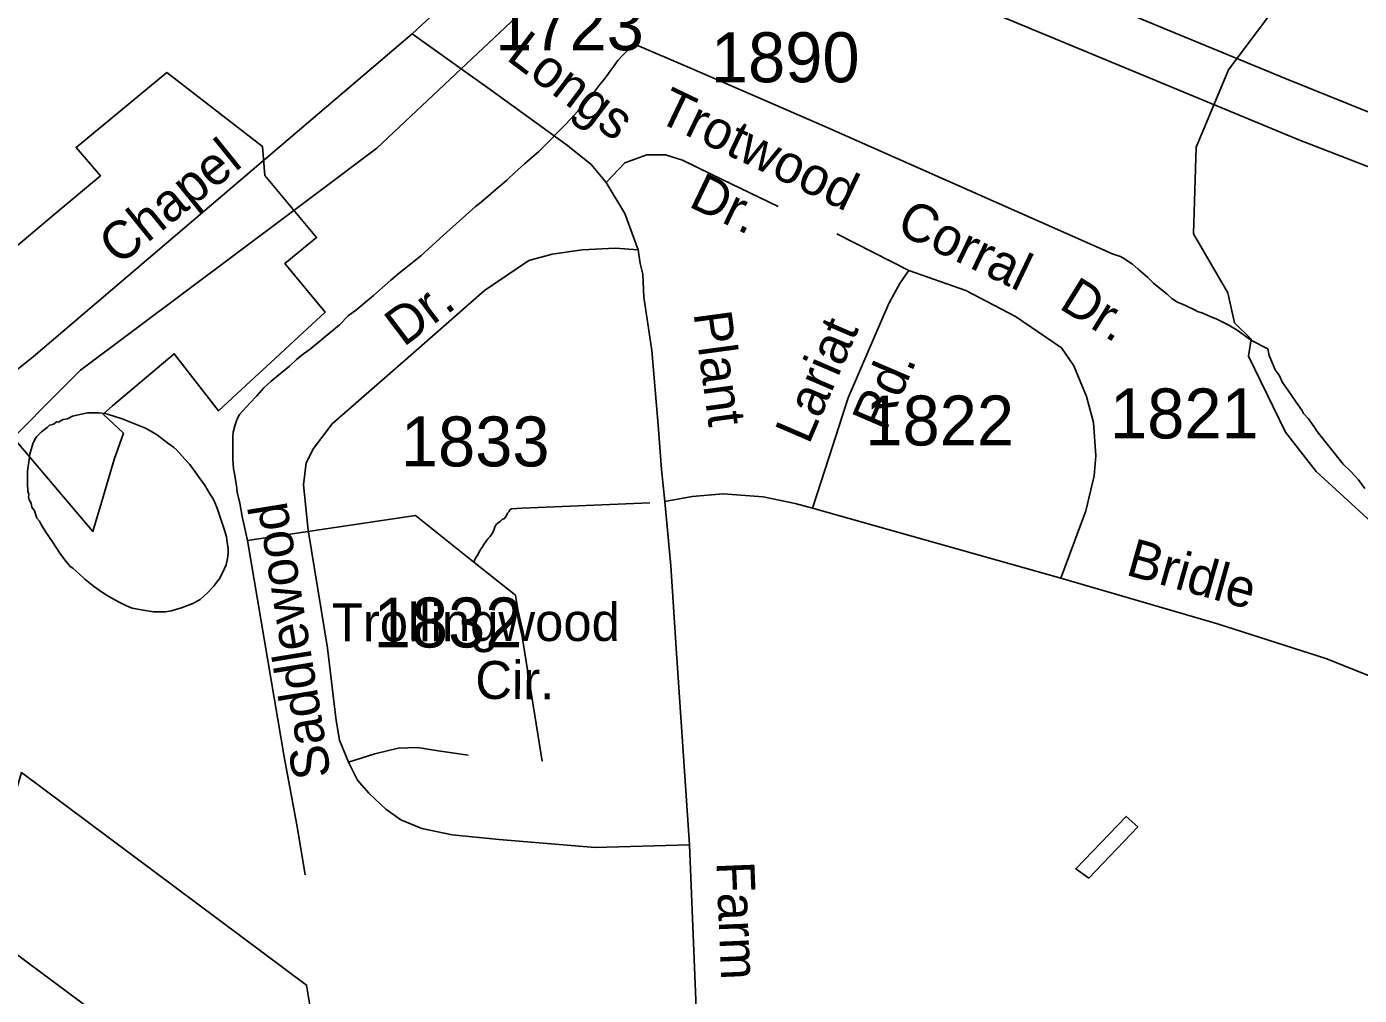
# Model space of a CAD drawing. Extents: x 2260773 to 2342389, y 552869 to 618546.
# Drawn here: x 2323921 to 2327254, y 582598 to 585022 of the extents above; entities that cross this region are included whole.
import ezdxf

# ---------------------------------------------------------------- set-up
doc = ezdxf.new("R2010")
doc.units = 0
for name, color, linetype in [('Exist Boundary Political City Limit New', 7, 'Continuous'), ('Exist Boundary Political Urban Extension UEB', 7, 'Continuous'), ('Exist Hydrographic Creek Single Shore', 7, 'Continuous'), ('Exist Hydrographic Misc Water Feature', 7, 'Continuous'), ('Exist Road Secondary Type 51 Attributed', 7, 'Continuous'), ('Exist Road Secondary Type 51 Label', 7, 'Continuous'), ('Exist Road Secondary Type 51 Number Label', 7, 'Continuous'), ('Map Preparation Boundary City Limit Buffer Line', 7, 'Continuous')]:
    doc.layers.add(name, color=color, linetype=linetype)

msp = doc.modelspace()

# ---------------------------------------------------------------- linework, layer by layer
at = {"layer": 'Exist Boundary Political City Limit New'}
for points in [[(2323668.2, 584281.2), (2323989.8, 584551.6), (2324105.5, 584648.9), (2324044.5, 584719.9), (2324271.2, 584907.1), (2324510.5, 584722.4), (2324516.8, 584649.4), (2324646.2, 584494.4), (2324567, 584429.8), (2324667.8, 584307.8), (2324578, 584224.9), (2324531.8, 584182), (2324491.8, 584144.8), (2324400.8, 584060.6), (2324290.2, 584203.5), (2324136, 584073), (2324112, 584052.8), (2324162.8, 584005.2), (2324140, 583939.2), (2324133, 583916.4), (2324103.8, 583817.4), (2324099.8, 583803.6), (2324086.5, 583758.7), (2323892, 583988.1)], [(2324673.5, 582308.4), (2324709.2, 582053.6), (2324723, 581957), (2324744, 581807.5), (2324535.8, 581891.1), (2324543.5, 581918.2), (2324427.2, 581964.1), (2324488.8, 582124.9), (2324365, 582177.6), (2324302, 582017.8), (2324046.8, 582140.8), (2324103.2, 582284.9), (2324184, 582486.4), (2324094.5, 582552.9), (2323814, 582761.1), (2323794, 582771.3), (2323907.8, 583155.7), (2324621.2, 582624.2), (2324673.5, 582308.4)]]:
    msp.add_lwpolyline(points, dxfattribs=at)
at = {"layer": 'Exist Boundary Political Urban Extension UEB'}
msp.add_line((2324646.2, 584604.9), (2324582.6, 584557.2), dxfattribs=at)
for points in [[(2329076.9, 583924.2), (2328749.3, 584100.5), (2327102.5, 584738.6), (2325517.5, 585397.2), (2325007.6, 584916.5)], [(2325007.6, 584916.5), (2324797, 584718), (2324646.2, 584604.9)], [(2324582.6, 584557.2), (2324055.9, 584162.3), (2323829.7, 583936.1)]]:
    msp.add_lwpolyline(points, dxfattribs=at)
at = {"layer": 'Exist Hydrographic Creek Single Shore'}
msp.add_lwpolyline([(2328673.6, 582831.9), (2328655.5, 582949.3), (2328477.5, 583188.3), (2328318.4, 583329.5), (2327950.6, 583432.7), (2327732.4, 583532.2), (2327548.5, 583603.6), (2327372.5, 583701.5), (2327145.5, 583908.9), (2327069.5, 584007.6), (2326976.6, 584197.4), (2326983.5, 584240.4), (2326941.5, 584281.3), (2326924.5, 584356.1), (2326839.4, 584503.6), (2326845.5, 584720.5), (2326926.5, 584914.1), (2327033.4, 585056.2)], dxfattribs=at)
at = {"layer": 'Exist Hydrographic Misc Water Feature'}
for points in [[(2324473.1, 583736.2), (2324460, 583796.1), (2324454.2, 583829.8), (2324447.2, 583857.6), (2324445.4, 583873.8), (2324442.9, 583887.9), (2324440.9, 583903.6), (2324438.6, 583915.7), (2324436.8, 583939.5), (2324436.4, 583945.6), (2324436.4, 583955.4), (2324436.4, 583965.5), (2324436.6, 583971.6), (2324436.2, 583977.7), (2324436.2, 583995.6), (2324437.8, 584007.5), (2324441.7, 584023.5), (2324445.4, 584035.5), (2324449.7, 584045.9), (2324453.2, 584051.8), (2324479.2, 584079.9), (2324496.7, 584098), (2324514.5, 584118.4), (2324532.5, 584134.7), (2324546.5, 584146.8), (2324578.5, 584172.9), (2324595.9, 584189.3), (2324613.5, 584203.2), (2324629.7, 584215.4), (2324703.2, 584276.2), (2324724.7, 584298.5), (2324746.4, 584314.6), (2324768.2, 584332.9), (2324788.5, 584349.3), (2324831.7, 584387.8), (2324853.5, 584406), (2324873.1, 584422.1), (2324906.8, 584448.3), (2324962.5, 584499.1), (2325043.3, 584571.7), (2325053.4, 584579.9), (2325075.1, 584598.2), (2325101, 584620.6), (2325109.2, 584626.7), (2325122.7, 584638.8), (2325142.2, 584657), (2325166.2, 584678.9), (2325202, 584709.6), (2325208, 584715.6), (2325269.1, 584778.2), (2325299, 584810.6), (2325330.6, 584846.8), (2325342.3, 584860.8), (2325354.4, 584876.9), (2325364, 584889.2), (2325372, 584899.3), (2325381.7, 584913.3), (2325389.7, 584923.5), (2325399.7, 584937.4), (2325411, 584949.5), (2325417.1, 584955.8), (2325425.3, 584963.9), (2325440.7, 584977.8), (2325579.3, 584919.3), (2325915, 584773), (2326637.8, 584453), (2326656.1, 584447), (2326666.1, 584441.4), (2326672.3, 584437.3), (2326686.4, 584427.5), (2326700.6, 584415.6), (2326718.2, 584399.9), (2326725, 584394.1), (2326738.9, 584380.2), (2326753.1, 584368.3), (2326772.9, 584352.4), (2326785.5, 584340.8), (2326799.4, 584333), (2326813.1, 584326.9), (2326821.1, 584323.2), (2326841.6, 584313.2), (2326849.4, 584309.2), (2326859.5, 584305.7), (2326879.4, 584297.9), (2326897.6, 584289.8), (2326905.4, 584286.2), (2326917.7, 584280.3), (2326925.5, 584276.3), (2326935.6, 584270.3), (2326947.9, 584262.4), (2326959.7, 584254.5), (2326975.9, 584242.8), (2326983.9, 584237.1), (2327024.8, 584215.6)], [(2327024.8, 584215.6), (2327028.4, 584199.6), (2327034.6, 584183.6), (2327043.2, 584163.7), (2327053.3, 584149.6), (2327061.2, 584131.8), (2327075.4, 584111.8), (2327095.5, 584082.4), (2327110.1, 584062.4), (2327113.9, 584054.5), (2327126.5, 584040.5), (2327140.6, 584020.5), (2327148.4, 584008.8), (2327213.4, 583927.6), (2327231.4, 583909.9), (2327251.9, 583887.8), (2327267.9, 583866.3)], [(2324248.1, 583999.5), (2324235.8, 584007.5), (2324225.8, 584013.4), (2324218, 584017), (2324159.8, 584040.4), (2324141.7, 584046.4), (2324123.5, 584052.3), (2324115.7, 584053.9), (2324101.7, 584056.1), (2324097.8, 584055.8), (2324091.9, 584055.9), (2324073.6, 584055.8), (2324061.7, 584053.5), (2324053.8, 584051.5), (2324043.5, 584049.4), (2324035.5, 584047.3), (2324023.4, 584041), (2324012.1, 584039.1), (2324000, 584032.8), (2323995.7, 584033), (2323990, 584028.6), (2323985.9, 584026.8), (2323977.9, 584024.8), (2323972.1, 584018.7), (2323958.2, 584008.3), (2323954.1, 584004.4), (2323950, 584000.2), (2323946.3, 583996.3), (2323942.4, 583990.4), (2323940.4, 583986.2), (2323938.5, 583982), (2323936.5, 583978.3), (2323928.9, 583952.3), (2323926.8, 583932.3), (2323925, 583922), (2323923.1, 583910.2), (2323923.3, 583904.1), (2323923.3, 583896), (2323923.3, 583886.2), (2323923.5, 583872), (2323923.7, 583866.2), (2323924.2, 583860.1), (2323926.2, 583852.1), (2323926, 583846), (2323927.6, 583838.1), (2323932.4, 583830.1), (2323934, 583820.1), (2323940.4, 583810.2), (2323946.3, 583792.3), (2323952.7, 583784.5), (2323957, 583776.5), (2323969.1, 583756.8), (2323985.5, 583732.9), (2324003.7, 583705), (2324015.4, 583689), (2324029.6, 583671.5), (2324036.1, 583667.3), (2324062.4, 583643.8), (2324066.3, 583639.6), (2324088, 583622.2), (2324110.6, 583606.2), (2324126.3, 583596.5), (2324150.7, 583582.7), (2324170.4, 583572.8), (2324185.2, 583567), (2324217, 583561.4), (2324238.9, 583557.7), (2324252.9, 583558), (2324268.6, 583558.1), (2324283, 583560), (2324296.9, 583564.3), (2324308.6, 583568.3), (2324336.7, 583578.6), (2324354.6, 583588.9), (2324372.2, 583604.9), (2324388, 583621.2), (2324396, 583631.3), (2324402.1, 583639.4), (2324411.8, 583657.4), (2324419.6, 583675.7), (2324423.5, 583691.7), (2324425.1, 583703.6), (2324425.3, 583717.4), (2324422.8, 583731.5), (2324420.6, 583745.7), (2324414.4, 583767.3), (2324397.6, 583817.3), (2324389.4, 583837.1), (2324385.7, 583843), (2324379.4, 583853.3), (2324373.4, 583863), (2324367.5, 583872.9), (2324329.1, 583926.5), (2324316.6, 583940.1), (2324296.3, 583962.2), (2324288.3, 583969.9), (2324274.2, 583979.8), (2324248.1, 583999.5)], [(2325479.5, 583830.9), (2325159.8, 583817.3), (2325133.8, 583815.2), (2325129.7, 583812.9), (2325127.8, 583809.2), (2325123.7, 583804.9), (2325120.2, 583796.9), (2325115.9, 583791.1), (2325110, 583788.7), (2325105.9, 583784.9), (2325100.1, 583780.9), (2325096, 583777), (2325092.1, 583770.7), (2325090.3, 583764.9), (2325086.4, 583756.6), (2325080.4, 583746.5), (2325074.7, 583740.5), (2325070.4, 583734.7), (2325064.7, 583726.6), (2325060.8, 583720.3), (2325056.7, 583714.4), (2325050.9, 583704.3), (2325048.9, 583700.2), (2325045, 583694.3), (2325042.9, 583690.1), (2325039, 583682.2)], [(2325039, 583682.2), (2324893.8, 583798.5), (2324473.1, 583736.2)], [(2324617.8, 582900.1), (2324598.4, 583015.7), (2324564.9, 583195.1), (2324473.1, 583736.2)], [(2325210.4, 583184.4), (2325143.8, 583599.5), (2325039, 583682.2)], [(2326576.9, 582891.2), (2326544.7, 582915.1), (2326671, 583046.1), (2326699.5, 583020.3), (2326576.9, 582891.2)]]:
    msp.add_lwpolyline(points, dxfattribs=at)
at = {"layer": 'Exist Road Secondary Type 51 Attributed'}
for p, q in [((2326127.5, 584411.8), (2325947, 584503.6)), ((2325886.4, 583816.9), (2326507.6, 583642.2))]:
    msp.add_line(p, q, dxfattribs=at)
for points in [[(2325403.9, 585580.5), (2325312.1, 585467.2), (2325198.2, 585337.2), (2325100.6, 585221.8), (2324985.3, 585097.5), (2324885.4, 585004.2)], [(2325403.9, 585580.5), (2327070.9, 584891.5), (2327889.1, 584561.4), (2329051.2, 584078.7), (2329166.4, 584028.3), (2329221.1, 584004.4), (2329309, 583947.7), (2329383.2, 583887.2), (2329447.6, 583830.5), (2329559.9, 583704.4), (2329766.9, 583446.5), (2329852.9, 583325.3), (2329899.8, 583229.5), (2329917.3, 583184.6)], [(2324885.4, 585004.2), (2323937.9, 584196.7), (2323711.5, 584014.7), (2323367.7, 583704.6), (2322777.6, 583052.4), (2322674, 582938), (2322644.5, 582899.3)], [(2324885.4, 585004.2), (2325007.6, 584916.5), (2325074, 584868.8), (2325273.7, 584724.5), (2325332.5, 584676.8), (2325370.2, 584632.4)], [(2325370.2, 584632.4), (2325416.8, 584681.2), (2325472.2, 584701.2), (2325518.8, 584701.2), (2325561, 584687.9), (2325634.2, 584652.3), (2325800.6, 584572.4)], [(2325370.2, 584632.4), (2325416.8, 584554.7), (2325450, 584463.6)], [(2324725.7, 583181.6), (2324703.5, 583237.1), (2324694.6, 583285.9), (2324673.5, 583466.9), (2324624.7, 583762.1), (2324613.6, 583875.3), (2324620.3, 583930.8), (2324638, 583966.4), (2324684.6, 584028.5), (2324888.7, 584206.1), (2325066.2, 584361.5), (2325177.2, 584437), (2325234.8, 584452.5), (2325310.3, 584463.6), (2325392.4, 584468.1), (2325450, 584463.6)], [(2325450, 584463.6), (2325455.6, 584429.2), (2325462.3, 584402.6), (2325464.5, 584344.9), (2325484.4, 584211.7), (2325500, 584025.2), (2325508.8, 583914.2), (2325517.3, 583833.9)], [(2325886.4, 583816.9), (2325927.8, 583945.6), (2325975.1, 584093.6), (2326029.8, 584219.4), (2326077.2, 584329), (2326105.3, 584380.8), (2326127.5, 584411.8)], [(2326507.6, 583642.2), (2326569.7, 583811), (2326590.4, 583898.3), (2326594.8, 583948.6), (2326588.9, 584031.5), (2326571.2, 584096.6), (2326540.1, 584173.6), (2326509.1, 584218), (2326393.7, 584296.4), (2326269.4, 584361.5), (2326127.5, 584411.8)], [(2325517.3, 583833.9), (2325585.4, 583846.5), (2325663, 583853.1), (2325762.8, 583845.8), (2325842.9, 583828.6), (2325886.4, 583816.9)], [(2325517.3, 583833.9), (2325532.1, 583673.3), (2325545.4, 583466.9), (2325578.7, 582974.8)], [(2326507.6, 583642.2), (2326898.8, 583527.6), (2327172.4, 583440.2), (2327463.8, 583323.3), (2327602.8, 583270), (2328057.6, 583139.1), (2328114.6, 583122), (2328158.2, 583100.6), (2328189.3, 583072.5), (2328205.5, 583041.4), (2328218.9, 583005.9), (2328221.8, 582971.8), (2328214.4, 582934.8)], [(2324725.7, 583181.6), (2324791.5, 583202.5), (2324850.3, 583216.4), (2324898.2, 583218.8), (2324949.8, 583210.5), (2325025.2, 583199.4)], [(2325578.7, 582974.8), (2325342.8, 582968.1), (2325102.8, 582988.5), (2324985.3, 582999.6), (2324909.5, 583015.5), (2324856.6, 583037.3), (2324818.9, 583063.9), (2324776.7, 583103.9), (2324748.2, 583136.8), (2324725.7, 583181.6)], [(2325578.7, 582974.8), (2325616.4, 582055), (2325639.4, 581485.9), (2325639.1, 581473.5), (2325637.8, 581413)]]:
    msp.add_lwpolyline(points, dxfattribs=at)
at = {"layer": 'Map Preparation Boundary City Limit Buffer Line'}
for points in [[(2323668.2, 584281.2), (2323989.8, 584551.6), (2324105.5, 584648.9), (2324044.5, 584719.9), (2324271.2, 584907.1), (2324510.5, 584722.4), (2324516.8, 584649.4), (2324646.2, 584494.4), (2324567, 584429.8), (2324667.8, 584307.8), (2324578, 584224.9), (2324531.8, 584182), (2324491.8, 584144.8), (2324400.8, 584060.6), (2324290.2, 584203.5), (2324136, 584073), (2324112, 584052.8), (2324162.8, 584005.2), (2324140, 583939.2), (2324133, 583916.4), (2324103.8, 583817.4), (2324099.8, 583803.6), (2324086.5, 583758.7), (2323892, 583988.1)], [(2324673.5, 582308.4), (2324709.2, 582053.6), (2324723, 581957), (2324744, 581807.5), (2324535.8, 581891.1), (2324543.5, 581918.2), (2324427.2, 581964.1), (2324488.8, 582124.9), (2324365, 582177.6), (2324302, 582017.8), (2324046.8, 582140.8), (2324103.2, 582284.9), (2324184, 582486.4), (2324094.5, 582552.9), (2323814, 582761.1), (2323794, 582771.3), (2323907.8, 583155.7), (2324621.2, 582624.2), (2324673.5, 582308.4)]]:
    msp.add_lwpolyline(points, dxfattribs=at)

# ---------------------------------------------------------------- texts
at = {"layer": 'Exist Road Secondary Type 51 Label'}
for s, rotation, p in [('Longs', 322.9611, (2325117.5, 584941.1)), ('Trotwood', 334.4068, (2325492.8, 584787.3)), ('Chapel', 38.9075, (2324151.2, 584422.2)), ('Dr.', 334.4068, (2325573.4, 584573.3)), ('Corral', 334.44, (2326091.9, 584507.9)), ('Dr.', 328.2331, (2326499.7, 584318.7)), ('Dr.', 37.0525, (2324863.8, 584219.1)), ('Plant', 277.6938, (2325588.4, 584305.1)), ('Lariat', 66.7314, (2325877.2, 583974.3)), ('Rd.', 66.7314, (2326069.4, 584005.5)), ('Saddlewood', 99.2202, (2324682.4, 583147.3)), ('Bridle', 344.3219, (2326666.8, 583651.3)), ('Trollingwood', 0.0884, (2324684.3, 583484)), ('Cir.', 359.6837, (2325042.8, 583340.1)), ('Farm', 272.3372, (2325645.7, 582931.9))]:
    msp.add_text(s, height=95, rotation=rotation, dxfattribs=at).set_placement(p)
at = {"layer": 'Exist Road Secondary Type 51 Number Label'}
for s, p in [('1723', (2325092.7, 584962.8)), ('1890', (2325632.1, 584882.8)), ('1821', (2326630.3, 583991.8)), ('1822', (2326018.4, 583974.1)), ('1833', (2324856.8, 583921.7)), ('1832', (2324788.9, 583468.7))]:
    msp.add_text(s, height=125, dxfattribs=at).set_placement(p)

doc.saveas('drawing.dxf')
